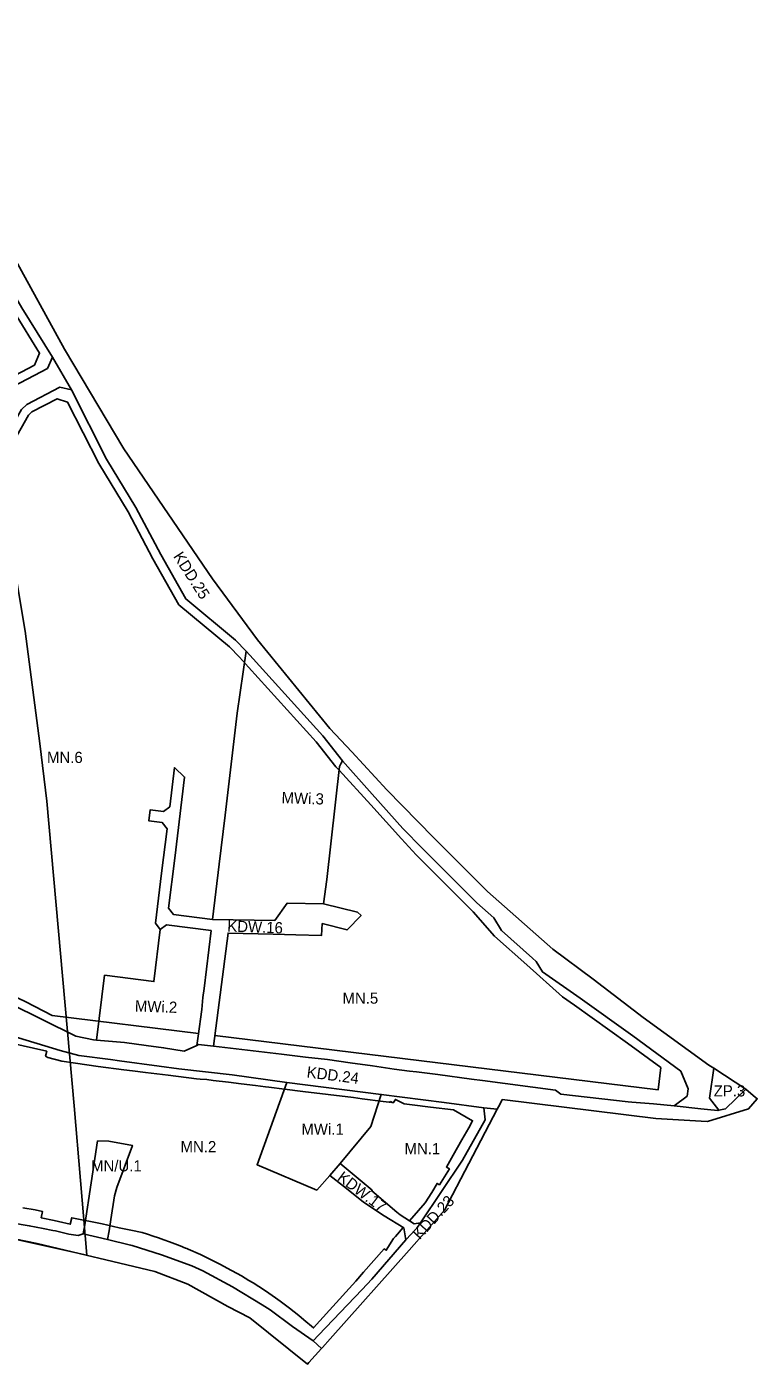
# Model space of a CAD drawing. Extents: x 7418991 to 7423142, y 5547704 to 5549547.
# Drawn here: x 7420687 to 7421013, y 5547704 to 5548302 of the extents above; entities that cross this region are included whole.
import ezdxf

# ---------------------------------------------------------------- set-up
doc = ezdxf.new("R2010")
doc.units = 0
for name, color, linetype in [('LIN_Linia Zabudowy Nieprzekraczalna', 7, 'Continuous'), ('LIN_linie_rozgraniczajace', 7, 'Continuous'), ('TRS_strefa ograniczen tunelu', 7, 'Continuous'), ('TXT_Oznaczenia_przeznaczen', 7, 'Continuous')]:
    doc.layers.add(name, color=color, linetype=linetype)

msp = doc.modelspace()

# ---------------------------------------------------------------- linework, layer by layer
at = {"layer": 'LIN_Linia Zabudowy Nieprzekraczalna'}
msp.add_line((7420698.03, 5547859.75), (7420763.47, 5547851.72), dxfattribs=at)
for points in [[(7420678.43, 5548144.48), (7420690.03, 5548150.52), (7420692.35, 5548155.89), (7420681.06, 5548174.17)], [(7420826.38, 5547969.48), (7420824.89, 5547971), (7420816.06, 5547982.21), (7420785.87, 5548015.55), (7420781.84, 5548020.01), (7420777.28, 5548024.67), (7420754.72, 5548043.42), (7420743.04, 5548063.92), (7420731.92, 5548084.98), (7420718.82, 5548106.54), (7420704.88, 5548134.1), (7420700.29, 5548135.57), (7420688.95, 5548129.66), (7420687.39, 5548128.19), (7420672.76, 5548102.54), (7420656.75, 5548109.36), (7420643.05, 5548121.37), (7420629.56, 5548131.5), (7420615.46, 5548140.9), (7420604.78, 5548147.83), (7420596.96, 5548152.58)], [(7420886.36, 5547906.13), (7420860.76, 5547931.67), (7420854.25, 5547938.83), (7420840.5, 5547953.95), (7420826.38, 5547969.48)], [(7420770.81, 5547850.82), (7420969.08, 5547826.51), (7420970.3, 5547836.43), (7420955.38, 5547847.38), (7420931.64, 5547864.31), (7420926.32, 5547868.11), (7420910.33, 5547882.37), (7420895.92, 5547895.21), (7420886.36, 5547906.13)], [(7420674.38, 5547871.79), (7420679.11, 5547869.24), (7420686.18, 5547865.83), (7420698.03, 5547859.75)], [(7420857.78, 5547768), (7420861.81, 5547772.55), (7420864.78, 5547776.01), (7420867.76, 5547780.56), (7420870.17, 5547784.7), (7420871.26, 5547784.04), (7420875.73, 5547791.14), (7420874.37, 5547791.99), (7420877.4, 5547797.35), (7420881.32, 5547804.14), (7420881.32, 5547804.14), (7420884.38, 5547809.5), (7420884.38, 5547809.5), (7420886.07, 5547812.71), (7420877.6, 5547817.52), (7420867.25, 5547818.75), (7420858.99, 5547819.76), (7420855.46, 5547820.2), (7420851.54, 5547822.25), (7420850.75, 5547820.79), (7420850.03, 5547820.88), (7420849.35, 5547821.24), (7420849.21, 5547820.98), (7420848.71, 5547821.04), (7420846.06, 5547821.34), (7420836.7, 5547822.49), (7420832.8, 5547823.02), (7420810.18, 5547825.78), (7420801.87, 5547826.84), (7420794.89, 5547827.74), (7420793.4, 5547827.92), (7420788.99, 5547828.44), (7420782.6, 5547829.21), (7420776.84, 5547829.91), (7420770.07, 5547830.7), (7420767.18, 5547831.08), (7420764.16, 5547831.36), (7420762.48, 5547831.51), (7420749.89, 5547833.05), (7420739.74, 5547834.27), (7420733.87, 5547834.96), (7420730.03, 5547835.45), (7420718.58, 5547836.97), (7420708.39, 5547838.41), (7420702.33, 5547839.34), (7420696.1, 5547841.04), (7420695.02, 5547841.55), (7420695.53, 5547843.78), (7420679.06, 5547847.58)], [(7420684.85, 5547773.77), (7420690.32, 5547772.78), (7420693.68, 5547772.07), (7420693.07, 5547769.34), (7420698.84, 5547768.03), (7420700.82, 5547767.58), (7420706.09, 5547766.38), (7420706.76, 5547769.35), (7420720.29, 5547766.58), (7420727.96, 5547764.87), (7420733.12, 5547763.79), (7420738.25, 5547762.69)], [(7420758.76, 5547755.27), (7420764.33, 5547752.81), (7420768.85, 5547750.66), (7420773.22, 5547748.47), (7420776.28, 5547746.82), (7420782.62, 5547743.32), (7420786.04, 5547741.22), (7420787.84, 5547740.18), (7420792.91, 5547736.9), (7420794.91, 5547735.6), (7420796.41, 5547734.51), (7420797.84, 5547733.54), (7420800, 5547731.99), (7420802.37, 5547730.24), (7420804.23, 5547728.83), (7420808.29, 5547725.64), (7420810.57, 5547723.73), (7420814.97, 5547720.08), (7420822.09, 5547728.03), (7420833.77, 5547741.02), (7420837.24, 5547744.99), (7420846.51, 5547755.35), (7420847.43, 5547754.78), (7420850.72, 5547760.05), (7420851.52, 5547760.95), (7420855.06, 5547764.93)]]:
    msp.add_lwpolyline(points, dxfattribs=at)
for start, end in [(67.98101, 72.5104), (67.71, 67.98101)]:
    msp.add_arc((7420659.98, 5547514.31), 260.42, start, end, dxfattribs=at)
at = {"layer": 'LIN_linie_rozgraniczajace'}
for p, q in [((7420698.13, 5548154.14), (7420695.95, 5548149.1)), ((7420706.58, 5548139.6), (7420698.13, 5548154.14)), ((7420680.77, 5548141.18), (7420695.95, 5548149.1)), ((7420686.61, 5548132.95), (7420701.45, 5548140.69)), ((7420706.58, 5548139.6), (7420701.45, 5548140.69)), ((7420722.32, 5548108.48), (7420706.58, 5548139.6)), ((7420721.34, 5547877.83), (7420717.78, 5547848.8)), ((7420679.05, 5547865.14), (7420708.53, 5547850.48)), ((7420979.23, 5547834.84), (7420982.51, 5547826.94)), ((7420991.98, 5547822.72), (7420994.03, 5547836.15)), ((7420923.21, 5547826.38), (7420925.52, 5547824.57)), ((7420982.02, 5547823.73), (7420982.51, 5547826.94)), ((7420982.02, 5547823.73), (7420976.29, 5547819.29)), ((7420991.98, 5547822.72), (7420996.22, 5547817.42)), ((7420995.74, 5547817.32), (7420991.23, 5547817.78))]:
    msp.add_line(p, q, dxfattribs=at)
for points in [[(7420698.13, 5548154.14), (7420684.48, 5548176.24), (7420671.11, 5548198.8), (7420657.11, 5548221.03), (7420648.92, 5548232.68), (7420641.55, 5548243.41), (7420630.32, 5548259.67), (7420620.24, 5548274.37), (7420614.65, 5548282.71), (7420608.78, 5548291.44), (7420605.02, 5548297.38), (7420605.58, 5548297.78), (7420603.55, 5548300.79), (7420602.39, 5548301.92)], [(7420680.09, 5548200.38), (7420703.55, 5548157.78), (7420730.03, 5548113.11), (7420769.72, 5548055), (7420789.83, 5548027.7), (7420822.17, 5547988.03), (7420832.1, 5547977.67), (7420847.71, 5547960.69), (7420868.59, 5547939.4), (7420892.8, 5547915.24), (7420921.94, 5547889.4), (7420939.99, 5547875.99), (7420962.38, 5547858.79), (7420991.78, 5547837.62), (7420994.03, 5547836.15), (7421008.35, 5547826.79), (7421011.62, 5547824.05), (7421013.42, 5547822.55), (7421009.55, 5547817.96), (7420991.17, 5547812.4), (7420988.28, 5547812.56), (7420968, 5547813.7), (7420899.36, 5547822.15), (7420898.21, 5547819.95), (7420897.09, 5547817.81)], [(7420671.05, 5548107.62), (7420684.21, 5548130.7), (7420686.61, 5548132.95)], [(7420722.32, 5548108.48), (7420735.4, 5548086.95), (7420746.55, 5548065.84), (7420757.84, 5548046.03), (7420779.99, 5548027.61), (7420784.75, 5548022.75), (7420787.89, 5548019.28)], [(7420784.75, 5548022.75), (7420780.74, 5547994.97), (7420775.31, 5547949.34), (7420772.72, 5547927.5), (7420769.76, 5547902.67)], [(7420827.9, 5547973.65), (7420819.12, 5547984.79), (7420787.89, 5548019.28)], [(7420769.76, 5547902.67), (7420752.22, 5547904.99), (7420750.05, 5547907.8), (7420752.8, 5547930.13), (7420757.24, 5547966.35), (7420752.73, 5547970.59), (7420750.59, 5547953.12), (7420747.81, 5547950.98), (7420741.86, 5547951.76), (7420741.24, 5547946.79), (7420747.2, 5547946.01), (7420749.36, 5547943.2), (7420746.93, 5547923.35), (7420744.18, 5547901.02), (7420746.36, 5547898.21), (7420749.14, 5547900.36), (7420769.14, 5547897.71)], [(7420827.9, 5547973.65), (7420827.32, 5547972.53), (7420826.56, 5547971.06), (7420820.89, 5547920.55), (7420819.35, 5547909.74)], [(7420863.62, 5547934.47), (7420854.88, 5547943.33), (7420841.1, 5547958.81), (7420827.9, 5547973.65)], [(7420895.52, 5547903.48), (7420888, 5547910.14), (7420883.76, 5547914.37), (7420868.71, 5547929.39), (7420863.62, 5547934.47)], [(7420770.19, 5547846.01), (7420776.68, 5547896.65), (7420796.79, 5547896.12), (7420807.03, 5547895.89), (7420818.45, 5547895.53), (7420818.78, 5547900.83), (7420829.91, 5547898.05), (7420836.19, 5547904.48), (7420834.6, 5547905.94), (7420819.35, 5547909.74), (7420803.08, 5547909.98), (7420797.57, 5547902.24)], [(7420721.34, 5547877.83), (7420743.48, 5547874.89), (7420746.36, 5547898.21)], [(7420797.57, 5547902.24), (7420769.76, 5547902.67)], [(7420912.91, 5547885.42), (7420899.02, 5547897.81), (7420895.52, 5547903.48)], [(7420769.14, 5547897.71), (7420765.95, 5547871.9), (7420765.43, 5547867.8), (7420765.11, 5547864.22), (7420764.89, 5547862.38), (7420763.31, 5547850.54), (7420762.75, 5547846.37)], [(7420934.12, 5547867.46), (7420917.41, 5547879.27), (7420914.54, 5547883.97), (7420912.91, 5547885.42)], [(7420979.23, 5547834.84), (7420957.73, 5547850.62), (7420934.12, 5547867.46)], [(7420802.95, 5547829.83), (7420778.55, 5547833.17), (7420754.72, 5547835.97), (7420745.87, 5547837.13), (7420728.04, 5547839.49), (7420724.08, 5547840.03), (7420709.97, 5547841.93), (7420701.54, 5547844.16), (7420679.43, 5547850.84)], [(7420756.97, 5547843.76), (7420747.8, 5547845.32), (7420739.97, 5547846.37), (7420730.38, 5547847.64), (7420717.78, 5547848.8), (7420716.46, 5547848.92), (7420708.53, 5547850.48)], [(7420770.19, 5547846.01), (7420763.52, 5547846.72), (7420762.75, 5547846.37), (7420756.97, 5547843.76)], [(7420923.21, 5547826.38), (7420890.47, 5547830.71), (7420885.64, 5547831.36), (7420870.59, 5547833.37), (7420860.94, 5547834.54), (7420857.84, 5547834.92), (7420850.92, 5547835.81), (7420841.26, 5547837.18), (7420831.28, 5547838.61), (7420821.21, 5547840.02), (7420811.29, 5547841.19), (7420800.52, 5547842.48), (7420790.37, 5547843.67), (7420770.19, 5547846.01)], [(7420995.74, 5547817.32), (7420996.22, 5547817.42), (7420999.23, 5547818.03), (7421008.35, 5547826.79)], [(7420897.09, 5547817.81), (7420891.11, 5547818.53), (7420873.41, 5547820.8), (7420845.23, 5547824.48)], [(7420991.23, 5547817.78), (7420988.2, 5547818.09), (7420976.29, 5547819.29), (7420967.03, 5547820.23), (7420957.33, 5547820.96), (7420955.63, 5547821.15), (7420925.52, 5547824.57)], [(7420891.11, 5547818.53), (7420891.65, 5547813.05), (7420881.48, 5547795.03), (7420862.69, 5547767), (7420861.07, 5547764.59), (7420856.24, 5547759.39), (7420841, 5547741.83), (7420836.65, 5547737.27), (7420817.13, 5547716.79), (7420814.72, 5547714.26)], [(7420897.09, 5547817.81), (7420884.39, 5547793.52), (7420873.47, 5547772.64), (7420857.68, 5547754.89), (7420822.3, 5547715.14), (7420818.92, 5547711.34), (7420818.5, 5547710.87)], [(7420718.32, 5547803.77), (7420712.54, 5547766.16), (7420711.87, 5547762.15)], [(7420718.32, 5547803.77), (7420723.3, 5547803.5), (7420733.91, 5547801.63), (7420726.9, 5547782.91), (7420725.88, 5547779.05), (7420724.2, 5547768.51), (7420723.5, 5547763.39), (7420722.79, 5547759.55)], [(7420862.69, 5547767), (7420859.99, 5547766.61), (7420853.6, 5547770.62), (7420852.17, 5547771.78), (7420840.93, 5547781.28), (7420841.16, 5547781.58), (7420826.83, 5547793.5)], [(7420822.18, 5547788.27), (7420829.65, 5547782.46), (7420837.23, 5547776.25), (7420846.53, 5547770.18), (7420855.34, 5547764.76), (7420856.24, 5547759.39)], [(7420711.87, 5547762.15), (7420709.6, 5547761.41), (7420705.44, 5547762.02), (7420699.52, 5547763.39), (7420698.32, 5547763.61), (7420693.9, 5547764.53), (7420687.7, 5547765.74), (7420684.1, 5547766.34), (7420671.79, 5547768.46), (7420669.45, 5547769.16), (7420655.8, 5547772.03), (7420655.15, 5547771.98), (7420645.84, 5547774.79)], [(7420818.5, 5547710.87), (7420812.85, 5547704.52), (7420812.21, 5547703.8), (7420786.38, 5547724.55), (7420776.64, 5547729.56), (7420758.68, 5547739.6), (7420743.97, 5547745.33), (7420691.26, 5547757.8), (7420643.94, 5547767.55)], [(7420818.5, 5547710.87), (7420814.72, 5547714.26), (7420805.5, 5547720.66), (7420795.45, 5547728.1), (7420791.97, 5547730.37), (7420778.59, 5547738.48), (7420765.35, 5547745.64), (7420760.54, 5547747.75), (7420746.85, 5547752.73), (7420733.73, 5547756.95), (7420733.06, 5547757.11), (7420722.79, 5547759.55), (7420711.87, 5547762.15)]]:
    msp.add_lwpolyline(points, dxfattribs=at)
msp.add_lwpolyline([(7420802.95, 5547829.83), (7420789.65, 5547792.99), (7420816.34, 5547781.65), (7420822.18, 5547788.27), (7420826.83, 5547793.5), (7420840.6, 5547810.09), (7420845.23, 5547824.48)], close=True, dxfattribs=at)
at = {"layer": 'TRS_strefa ograniczen tunelu'}
msp.add_line((7420612.79, 5547774.96), (7420713.56, 5547752.53), dxfattribs=at)
msp.add_lwpolyline([(7420713.56, 5547752.53), (7420707.81, 5547819.34), (7420695.62, 5547955.67), (7420692.42, 5547981.44), (7420685.92, 5548031.57), (7420666.24, 5548148.12), (7420652.97, 5548213.26), (7420639.17, 5548272.24)], dxfattribs=at)

# ---------------------------------------------------------------- texts
at = {"layer": 'TXT_Oznaczenia_przeznaczen'}
for s, rotation, p in [('KDD.25', 302.67901, (7420751.96, 5548065.08)), ('MWi.3', 357.99636, (7420800.53, 5547954.73)), ('KDW.16', 357.99636, (7420776.25, 5547897.31)), ('MWi.2', 357.99636, (7420734.91, 5547861.57)), ('KDD.24', 352.73488, (7420811.65, 5547832.11)), ('KDW.17', 322.93687, (7420825.19, 5547786.47)), ('KDD.23', 47.32921, (7420862.44, 5547759.24))]:
    msp.add_text(s, height=5, rotation=rotation, dxfattribs=at).set_placement(p)
for s, p in [('MN.6', (7420695.68, 5547972.67)), ('MN.5', (7420827.87, 5547865.03)), ('ZP.3', (7420993.93, 5547823.56)), ('MWi.1', (7420809.48, 5547806.44)), ('MN.2', (7420755.42, 5547798.6)), ('MN.1', (7420855.61, 5547797.72)), ('MN/U.1', (7420715.39, 5547790.04))]:
    msp.add_text(s, height=5, dxfattribs=at).set_placement(p)

doc.saveas('drawing.dxf')
